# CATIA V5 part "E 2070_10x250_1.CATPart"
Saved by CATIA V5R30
Part number: E 2070_10x250_1
Definition: E 2070_10x250_1
Nomenclature: E 2070_10x250_1
Source: Unknown
Description: PART--DESC
Bounding box of the stored display mesh (mm): x 0.75 to 68.75, y -4.99 to 4.99, z 39.5 to 49.5
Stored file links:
  E:\Bakalarka\Model\Forma_v7\E 2070_10x250_1.CATPart
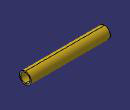
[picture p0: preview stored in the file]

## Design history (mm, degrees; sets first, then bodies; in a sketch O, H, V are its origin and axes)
Body1 "MANIFOLD_SOLID_BREP #156" (main body)
  Solid1: solid without history
  Pocket1: profile face of Solid1, direction along face of Solid1 reversed, length 183
  Pad1: profile face of Solid1, direction along face of Solid1, length 1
